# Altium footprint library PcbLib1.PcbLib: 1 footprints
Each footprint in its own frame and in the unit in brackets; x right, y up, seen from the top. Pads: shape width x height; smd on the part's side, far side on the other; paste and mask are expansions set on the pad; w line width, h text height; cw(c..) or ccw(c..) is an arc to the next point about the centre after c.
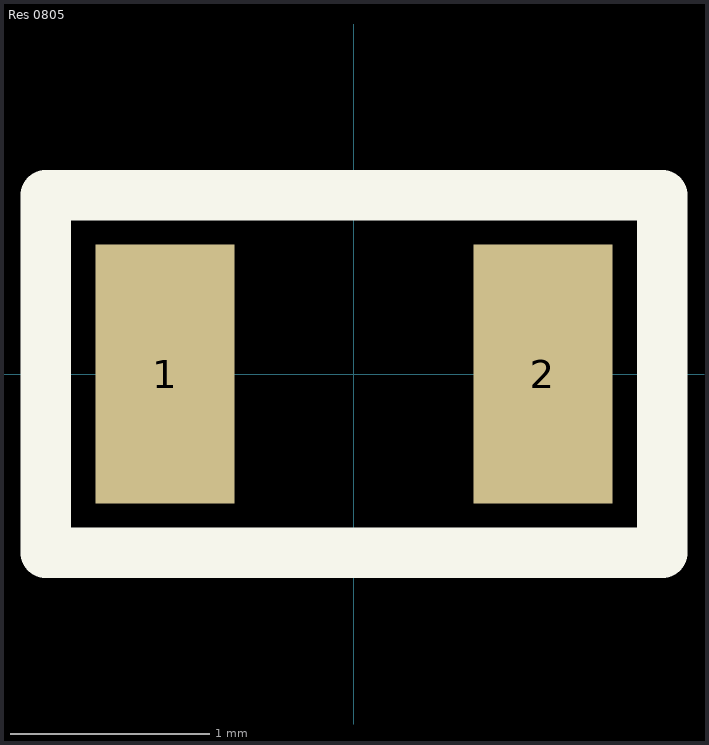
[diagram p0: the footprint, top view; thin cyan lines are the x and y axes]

## Res 0805 [mm]
pads (2):
  rect 0.7x1.3 smd: 1(-0.95,0) 2(0.95,0)
Top Overlay:
  lines w0.254: -1.55,-0.9 -1.55,0.9 1.55,0.9 1.55,-0.9 -1.55,-0.9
